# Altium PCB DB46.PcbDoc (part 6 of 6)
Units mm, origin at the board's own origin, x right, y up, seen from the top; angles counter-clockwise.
Board outline 82.2 x 113.2 mm, 8 copper layers (Top Layer, MidLayer1, MidLayer2, GND, MidLayer3, VCC, MidLayer4, Bottom Layer), stack 1.576 mm thick; 186 components, 477 nets, 1727 pads, 1538 vias.
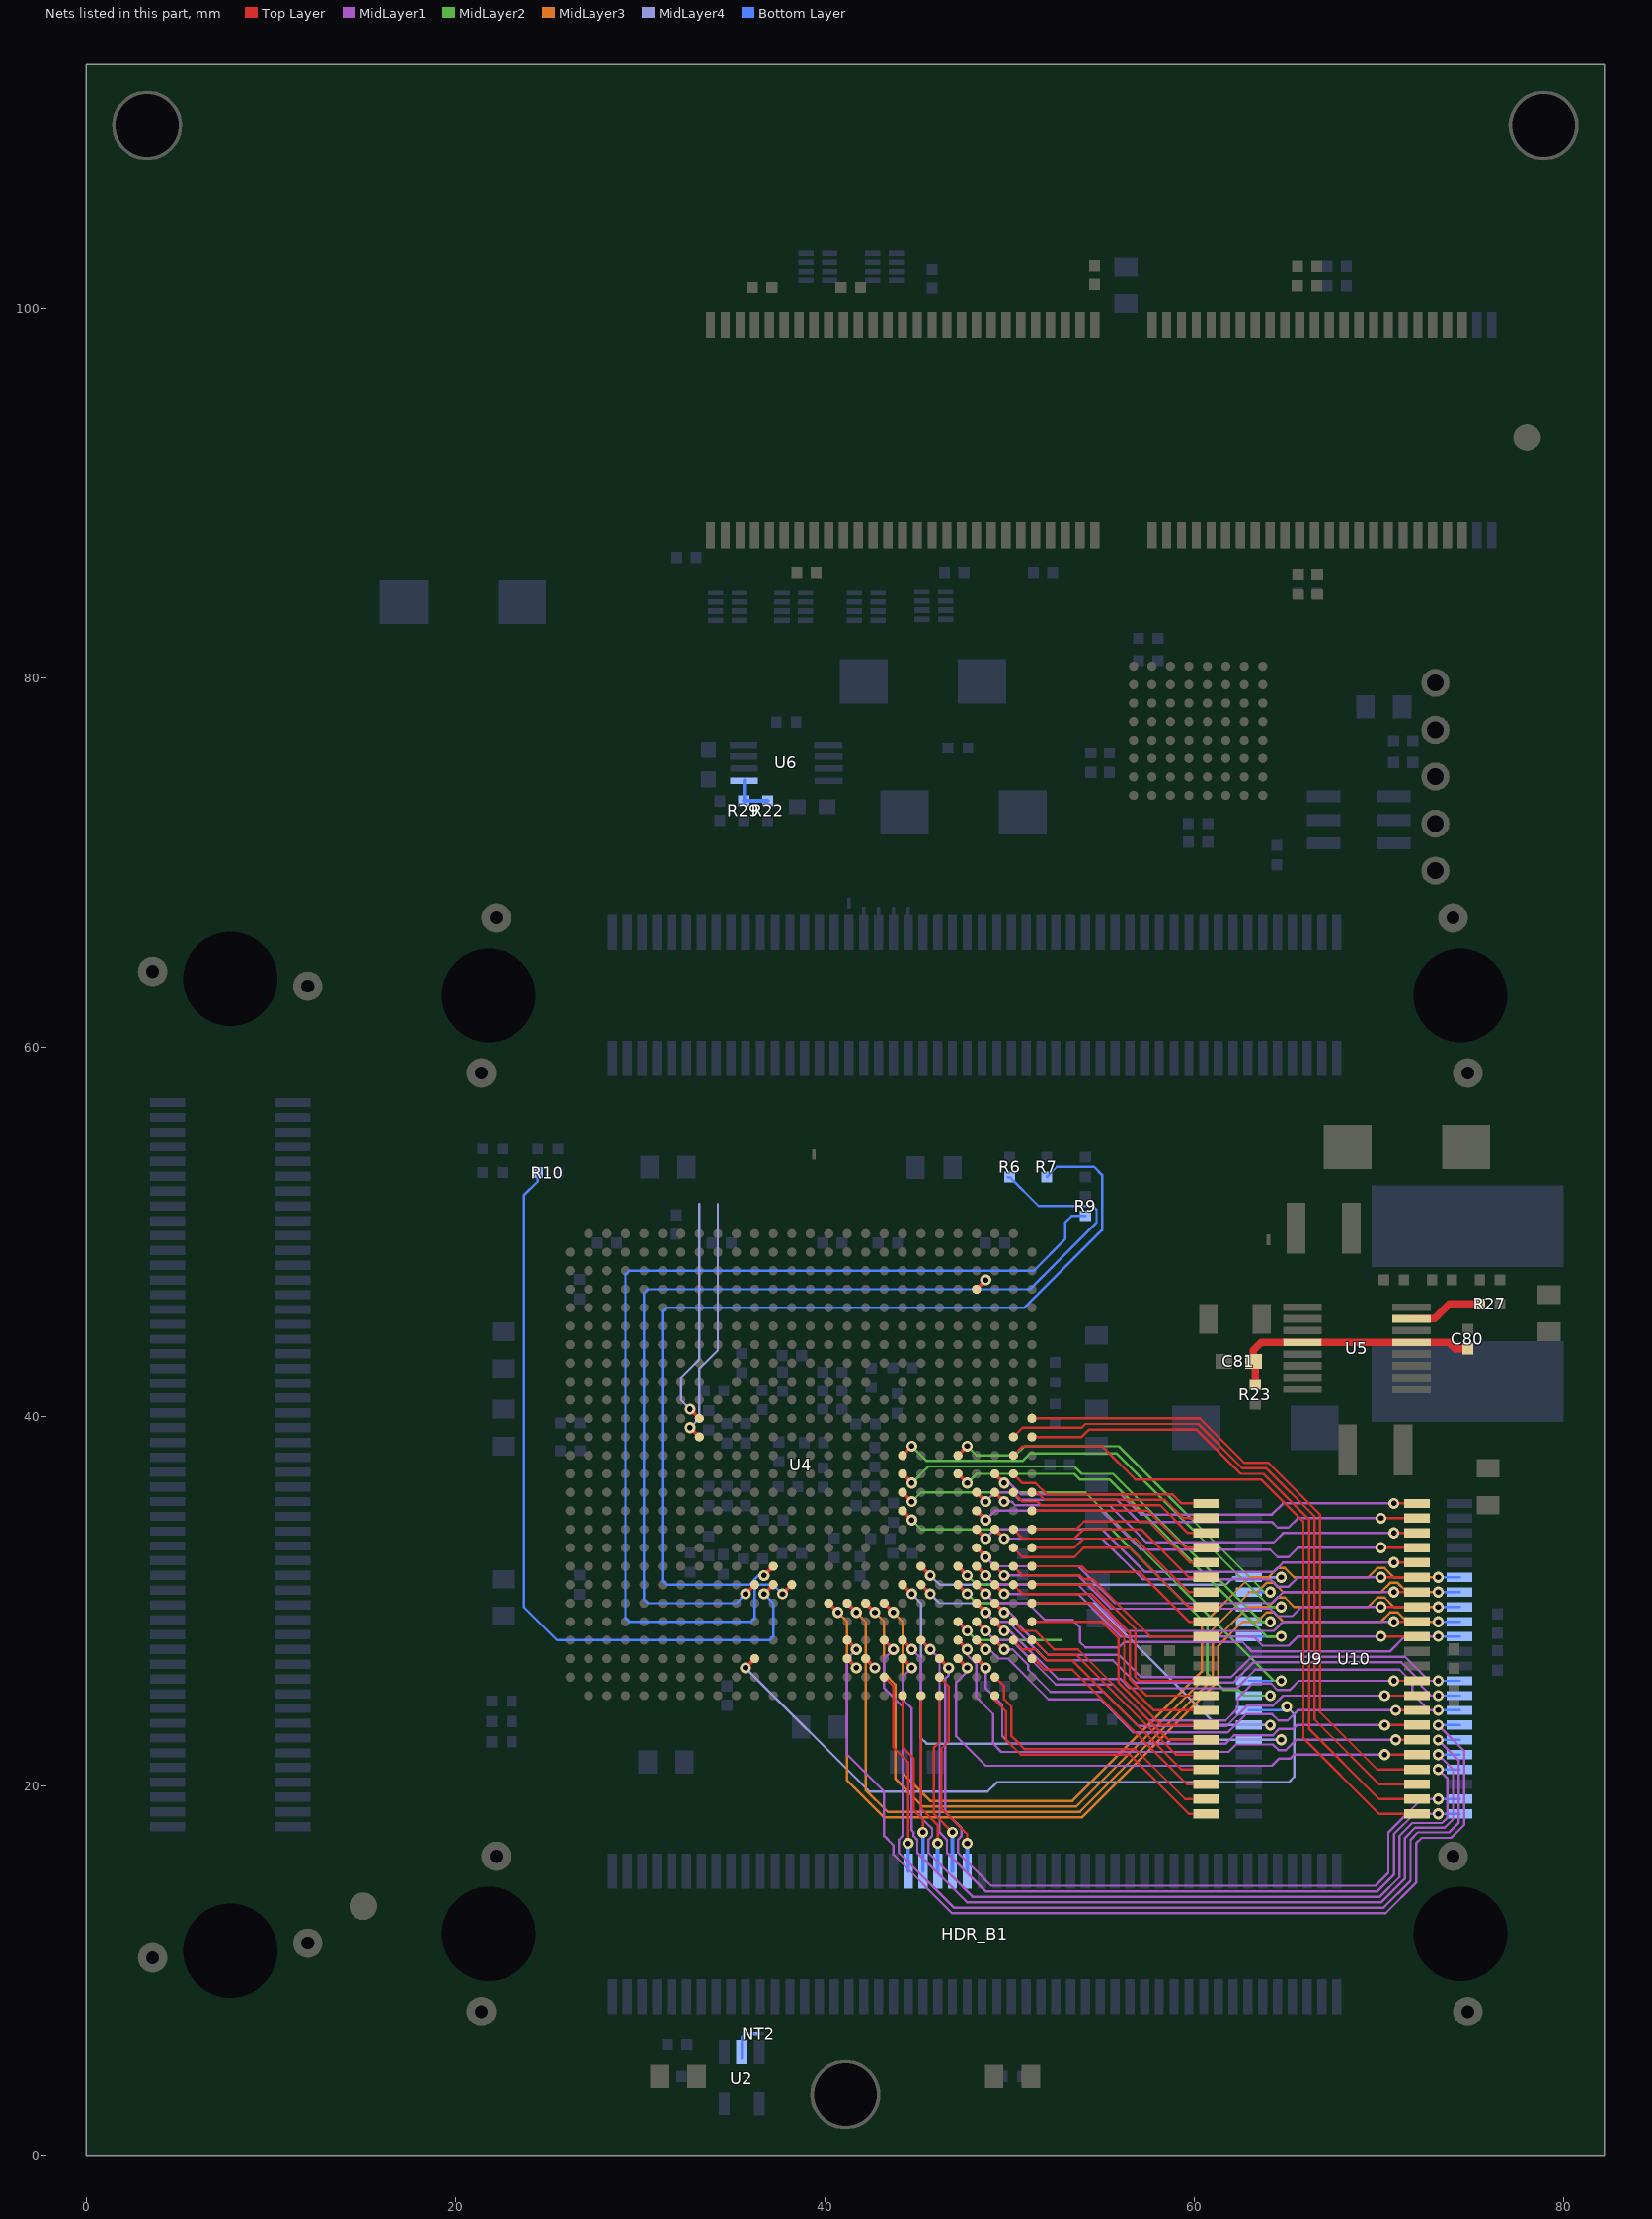
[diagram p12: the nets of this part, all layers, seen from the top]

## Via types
v1: diameter 0.6, hole 0.3, Top Layer to Bottom Layer, 904 vias
v2: diameter 0.6, hole 0.3, Top Layer to Bottom Layer, tented both sides, 506 vias
v3: diameter 0.7, hole 0.4, Top Layer to Bottom Layer, 127 vias
v4: diameter 0.6, hole 0.3, Top Layer to Bottom Layer, tented top, 1 vias

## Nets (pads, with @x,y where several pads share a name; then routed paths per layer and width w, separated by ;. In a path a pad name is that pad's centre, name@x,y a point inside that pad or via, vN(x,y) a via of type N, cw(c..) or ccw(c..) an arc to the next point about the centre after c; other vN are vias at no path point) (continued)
SRAM1_A16: U4.AD21 U10.43 | length 42.4
  Top Layer w0.2: U4.AD21@46.2,26.9 v1(46.7,26.4)
  MidLayer1 w0.127: v1(46.7,26.4) 46.7,26 46.5,25.8 46.5,23.3 46.5,23 46.5,18.6 47.4,17.7 47.4,17.3 47.2,17.1 47.2,16.4 48.994,14.606 69.806,14.606 70.5,15.3 70.5,17.5 72.3,19.3 v1(73.2,19.3)
  Bottom Layer w0.127: v1(73.2,19.3) U10.43@74.352,19.3
SRAM1_A17: U4.AC20 U10.44 | length 43.7
  Top Layer w0.2: U4.AC20@45.2,27.9 v1(45.7,27.4)
  MidLayer1 w0.127: v1(45.7,27.4) 46.2,26.9 46.2,23.3 46.2,23 46.2,17.5 46.6,17.1 46.6,16.4 48.694,14.306 69.906,14.306 70.8,15.2 70.8,17.4 71.9,18.5 v1(73.2,18.5)
  Bottom Layer w0.127: v1(73.2,18.5) U10.44@74.352,18.5
SRAM1_A18: U4.AA18 U10.28 | length 47.7
  Top Layer w0.2: U4.AA18@43.2,29.9 v1(43.7,29.4)
  MidLayer3 w0.127: v1(43.7,29.4) 44.2,28.9 44.2,23.3 44.2,23 44.2,20.7 45.7,19.2 53.4,19.2 60.4,26.2 60.4,28.7 63,31.3 64,31.3 64.5,31.8 64.9,31.8 65.4,31.3 69.4,31.3 69.9,31.8 70.3,31.8 70.8,31.3 v1(73.2,31.3)
  Bottom Layer w0.127: v1(73.2,31.3) U10.28@74.352,31.3
SRAM1_D0: U4.Y20 U10.7 | length 23.3
  Top Layer w0.2: U4.Y20@45.2,30.9 v1(45.7,30.4)
  MidLayer2 w0.127: v1@64.099,23.299 v1(64.105,23.299)
  MidLayer4 w0.127: v1(45.7,30.4) 46.2,29.9 52.8,29.9 53.1,29.9 54.6,29.9 61.2,23.299 v1(64.105,23.299)
  Bottom Layer w0.127: U10.7@62.952,23.3 v1(64.105,23.299) v1@64.205,23.299
SRAM1_D1: U4.AD11 U10.8 | length 39.7
  Top Layer w0.2: v1(35.7,26.4) U4.AD11@36.2,26.9
  MidLayer4 w0.127: v1(35.7,26.4) 42.4,19.7 48.8,19.7 49.3,20.2 65.1,20.2 65.4,20.5 65.4,23.9 v1(65,24.3)
  Bottom Layer w0.127: U10.8@62.952,24.1 64.8,24.1 v1(65,24.3)
  Bottom Layer w0.381: v1@35.592,26.4 v1(35.7,26.4)
SRAM1_D2: U4.T19 U10.9 | length 26.8
  Top Layer w0.2: U4.T19@44.2,34.9 v1(44.7,34.4)
  MidLayer2 w0.127: v1(44.7,34.4) 45.2,33.9 52.8,33.9 53.1,33.9 55.5,33.9 60.7,28.7 60.7,26.1 61.6,25.2 62.4,25.2 62.7,24.9 v1(64.105,24.9)
  Bottom Layer w0.127: U10.9@62.952,24.9 v1@64.205,24.9
SRAM1_D3: U4.R19 U10.10 | length 27
  Top Layer w0.2: U4.R19@44.2,35.9 v1(44.7,35.4)
  MidLayer2 w0.127: v1(44.7,35.4) 45.2,35.9 52.8,35.9 53.1,35.9 54.1,35.9 64.3,25.7 v1(64.7,25.7)
  Bottom Layer w0.127: U10.10@62.952,25.7 v1@64.8,25.7
SRAM1_D4: U4.P22 U10.13 | length 23.4
  Top Layer w0.2: U4.P22@47.2,36.9 v1(47.7,36.4)
  MidLayer2 w0.127: v1(47.7,36.4) 48.2,36.9 52.8,36.9 53.1,36.9 53.5,36.9 53.8,36.6 55.4,36.6 63.9,28.1 v1(64.7,28.1)
  Bottom Layer w0.127: U10.13@62.952,28.1 v1@64.8,28.1
SRAM1_D5: U4.P19 U10.14 | length 25.2
  Top Layer w0.2: U4.P19@44.2,36.9 v1(44.7,36.4)
  MidLayer2 w0.127: v1(44.7,36.4) 45.6,37.3 52.8,37.3 53.1,37.3 53.5,37.3 53.9,36.9 55.6,36.9 63.6,28.9 v1(64.105,28.9)
  Bottom Layer w0.127: U10.14@62.952,28.9 v1@64.205,28.9
SRAM1_D6: U4.N19 U10.15 | length 26.5
  Top Layer w0.178: U4.N19@44.2,37.9 v1(44.7,38.4)
  MidLayer2 w0.127: v1(44.7,38.4) 45.5,37.6 50.7,37.6 51.1,38 52.8,38 53.1,38 55.8,38 64.1,29.7 v1(64.7,29.7)
  Bottom Layer w0.127: U10.15@62.952,29.7 v1@64.8,29.7
SRAM1_D7: U4.N22 U10.16 | length 22.1
  Top Layer w0.2: U4.N22@47.2,37.9 v1(47.7,38.4)
  MidLayer2 w0.127: v1(47.7,38.4) 48.2,37.9 50.3,37.9 50.8,38.4 52.8,38.4 53.1,38.4 55.9,38.4 63.8,30.5 v1(64.105,30.5)
  Bottom Layer w0.127: U10.16@62.952,30.5 v1@64.205,30.5
SRAM1_D8: U4.AA17 U10.29 | length 48.3
  Top Layer w0.2: U4.AA17@42.2,29.9 v1(42.7,29.4)
  MidLayer3 w0.127: v1(42.7,29.4) 43.2,28.9 43.2,26.1 43.8,25.5 43.8,23.3 43.8,23 43.8,20.4 45.3,18.9 53.6,18.9 60.7,26 60.7,28.2 63,30.5 63.405,30.5 63.905,31 64.305,31 64.805,30.5 70.1,30.5 70.6,31 71,31 71.5,30.5 v1(73.2,30.5)
  Bottom Layer w0.127: v1(73.2,30.5) U10.29@74.352,30.5
SRAM1_D9: U4.AA16 U10.30 | length 49.8
  Top Layer w0.2: U4.AA16@41.2,29.9 v1(41.7,29.4)
  MidLayer3 w0.127: v1(41.7,29.4) 42.2,28.9 42.2,23.3 42.2,23 42.2,19.8 43.4,18.6 53.8,18.6 61,25.8 61,27.8 62.9,29.7 64,29.7 64.5,30.2 64.9,30.2 65.4,29.7 69.4,29.7 69.9,30.2 70.3,30.2 70.8,29.7 v1(73.2,29.7)
  Bottom Layer w0.127: v1(73.2,29.7) U10.30@74.352,29.7
SRAM1_D10: U4.AA15 U10.31 | length 50.3
  Top Layer w0.2: U4.AA15@40.2,29.9 v1(40.7,29.4)
  MidLayer3 w0.127: v1(40.7,29.4) 41.2,28.9 41.2,23.3 41.2,23 41.2,20.3 43.2,18.3 53.9,18.3 61.3,25.7 61.3,27.6 62.6,28.9 63.405,28.9 63.905,29.4 64.305,29.4 64.805,28.9 70.1,28.9 70.6,29.4 71,29.4 71.5,28.9 v1(73.2,28.9)
  Bottom Layer w0.127: v1(73.2,28.9) U10.31@74.352,28.9
SRAM1_D11: U4.Y23 U10.32 | length 28.7
  Top Layer w0.2: U4.Y23@48.2,30.9 v1(48.7,30.4)
  MidLayer1 w0.127: v1(48.7,30.4) 49.2,29.9 51,29.9 51.9,29 52.8,29 53.1,29 53.4,29 53.8,28.6 53.8,27.8 54.1,27.5 55.9,27.5 56.2,27.8 62.6,27.8 63.1,27.3 70.6,27.3 71.4,28.1 v1(73.2,28.1)
  Bottom Layer w0.127: v1(73.2,28.1) U10.32@74.352,28.1
SRAM1_D12: U4.AA24 U10.35 | length 27.9
  Top Layer w0.2: U4.AA24@49.2,29.9 v1(49.7,29.4)
  MidLayer1 w0.127: v1(49.7,29.4) 50,29.4 50.3,29.1 50.3,28.9 52.1,27.1 52.8,27.1 53.1,27.1 55.9,27.1 57.1,25.9 62,25.9 63.1,27 71.4,27 72.7,25.7 v1(73.2,25.7)
  Bottom Layer w0.127: v1(73.2,25.7) U10.35@74.352,25.7
SRAM1_D13: U4.AA23 U10.36 | length 29.3
  Top Layer w0.2: U4.AA23@48.2,29.9 v1(48.7,29.4)
  MidLayer1 w0.127: v1(48.7,29.4) 49.2,28.9 49.9,28.9 52,26.8 52.8,26.8 53.1,26.8 55.6,26.8 56.8,25.6 62.1,25.6 63.2,26.7 71.2,26.7 72.3,25.6 72.3,25.4 72.8,24.9 v1(73.2,24.9)
  Bottom Layer w0.127: v1(73.2,24.9) U10.36@74.352,24.9
SRAM1_D14: U4.AB24 U10.37 | length 28.3
  Top Layer w0.2: U4.AB24@49.2,28.9 v1(49.7,28.4)
  MidLayer1 w0.127: v1(49.7,28.4) 50,28.4 52.6,25.8 52.8,25.8 53.1,25.8 56,25.8 56.5,25.3 62.3,25.3 63.3,26.3 71.1,26.3 71.8,25.6 71.8,25 72.7,24.1 v1(73.2,24.1)
  Bottom Layer w0.127: v1(73.2,24.1) U10.37@74.352,24.1
SRAM1_D15: U4.AC16 U10.38 | length 55.6
  Top Layer w0.2: U4.AC16@41.2,27.9 v1(41.7,27.4)
  MidLayer1 w0.127: v1(41.7,27.4) 41.2,26.9 41.2,23.3 41.2,23 41.2,21.7 43.2,19.7 43.2,17.3 43.7,16.8 43.7,16.3 46.875,13.125 70.35,13.125 72,14.775 72,15.3 72,16.9 72.3,17.2 73.9,17.2 74.6,17.9 74.6,21.9 v1(73.2,23.3)
  Bottom Layer w0.127: v1(73.2,23.3) U10.38@74.352,23.3
SRAM1_NBHE: U4.AD19 U10.40 | length 49.5
  Top Layer w0.2: U4.AD19@44.2,26.9 v1(44.7,26.4)
  MidLayer1 w0.127: v1(44.7,26.4) 44.2,25.9 44.2,24.7 44.7,24.2 44.7,23.3 44.7,23 44.7,17.6 44.8,17.5 44.8,17.3 45,17.1 45,16.4 47.681,13.719 70.119,13.719 71.4,15 71.4,15.6 ; 71.4,15.6 71.4,17.2 71.946,17.746 73.546,17.746 74,18.2 74,20.9 v1(73.2,21.7)
  Bottom Layer w0.127: v1(73.2,21.7) U10.40@74.352,21.7
SRAM1_NBLE: U4.AC18 U10.39 | length 53.2
  Top Layer w0.2: U4.AC18@43.2,27.9 v1(43.7,27.4)
  MidLayer1 w0.127: v1(43.7,27.4) 43.2,26.9 43.2,25.3 44.2,24.3 44.2,23.3 44.2,23 44.2,17.3 44,17.1 44,16.4 46.975,13.425 70.25,13.425 71.7,14.875 71.7,15.4 71.7,17.1 72.092,17.492 73.792,17.492 74.3,18 74.3,21.4 v1(73.2,22.5)
  Bottom Layer w0.127: v1(73.2,22.5) U10.39@74.352,22.5
SRAM1_NCS: U4.Y19 U10.6 | length 30.3
  Top Layer w0.2: U4.Y19@44.2,30.9 v1(44.7,30.4)
  MidLayer4 w0.127: v1(44.7,30.4) 45.2,29.9 45.2,23.3 45.2,23 45.2,22.6 45.5,22.3 58.5,22.3 58.7,22.5 v1(64.7,22.5)
  Bottom Layer w0.127: U10.6@62.952,22.5 v1(64.7,22.5) v1@64.8,22.5
SRAM1_NOE: U4.AC19 U10.41 | length 51.3
  Top Layer w0.2: U4.AC19@44.2,27.9 v1(44.7,27.4)
  MidLayer1 w0.127: v1(44.7,27.4) 45.2,26.9 ; 45.2,24 45.2,26.9 ; v1(73.2,20.9) 73.7,20.4 73.7,18.3 73.4,18 71.8,18 71.1,17.3 71.1,15.7 71.1,15.075 70.037,14.012 47.987,14.012 45.6,16.4 45.6,17.1 45.8,17.3 45.8,17.7 45.7,17.8 45.2,18.3 45.2,23 45.2,23.3 45.2,26.9
  Bottom Layer w0.127: v1(73.2,20.9) U10.41@74.352,20.9
SRAM1_NWE: U4.W20 U10.17 | length 21.9
  Top Layer w0.2: U4.W20@45.2,31.9 v1(45.7,31.4)
  MidLayer4 w0.127: v1(45.7,31.4) 46.2,30.9 50.9,30.9 52.8,30.9 53.1,30.9 61.7,30.9 62.1,31.3 v1(64.7,31.3)
  Bottom Layer w0.127: U10.17@62.952,31.3 v1(64.7,31.3) v1@64.8,31.3
SRAM2_A0: U4.N25 U9.1 | length 37.2
  Top Layer w0.127: U4.N25@50.2,37.9 50.7,38.4 52.8,38.4 53.1,38.4 55,38.4 56.8,36.6 63.6,36.6 65.9,34.3 65.9,22.6 70,18.5 U9.1@72.052,18.5
SRAM2_A1: U4.M26 U9.2 | length 35.9
  Top Layer w0.127: U4.M26@51.2,38.9 52.8,38.9 53.1,38.9 53.9,38.9 54.3,39.3 60.1,39.3 62.5,36.9 63.737,36.9 66.2,34.437 66.2,23.1 70,19.3 U9.2@72.052,19.3
SRAM2_A2: U4.M25 U9.3 | length 36.7
  Top Layer w0.127: U4.M25@50.2,38.9 50.7,39.4 52.8,39.4 53.1,39.4 53.9,39.4 54.1,39.6 60.2,39.6 62.6,37.2 63.9,37.2 66.5,34.6 66.5,23.6 70,20.1 U9.3@72.052,20.1
SRAM2_A3: U4.L26 U9.4 | length 35
  Top Layer w0.127: U4.L26@51.2,39.9 52.8,39.9 53.1,39.9 60.3,39.9 62.7,37.5 64,37.5 66.8,34.7 66.8,24 69.9,20.9 U9.4@72.052,20.9
SRAM2_A4: U4.AD22 U9.5 | length 30.5
  Top Layer w0.127: v1(70.299,21.7) U9.5@72.052,21.7
  Top Layer w0.2: U4.AD22@47.2,26.9 v1(47.7,26.4)
  MidLayer1 w0.127: v1(47.7,26.4) 47.7,26.2 47.1,25.6 47.1,23.3 47.1,23 47.1,22.7 48.7,21.1 64.2,21.1 64.6,21.5 65.2,21.5 65.4,21.7 v1(70.299,21.7)
SRAM2_A5: U4.U23 U9.18 | length 25.4
  Top Layer w0.127: v1@70.8,32.1 U9.18@72.052,32.1
  Top Layer w0.2: U4.U23@48.2,33.9 v1(48.7,33.4)
  MidLayer1 w0.127: v1(48.7,33.4) 49.2,33.9 52.1,33.9 52.8,33.9 53.1,33.9 55,33.9 57.3,31.6 64.3,31.6 64.8,32.1 v1(70.8,32.1)
SRAM2_A6: U4.T23 U9.19 | length 25.5
  Top Layer w0.127: v1(70.1,32.9) U9.19@72.052,32.9
  Top Layer w0.2: U4.T23@48.2,34.9 v1(48.7,34.4)
  MidLayer1 w0.127: v1(48.7,34.4) 49.2,34.9 52.8,34.9 53.1,34.9 55,34.9 57.1,32.8 64.1,32.8 64.5,32.4 65.1,32.4 65.6,32.9 v1(70.1,32.9)
SRAM2_A7: U4.R24 U9.20 | length 24.2
  Top Layer w0.127: v1(70.8,33.7) U9.20@72.052,33.7
  Top Layer w0.2: U4.R24@49.2,35.9 v1(49.7,35.4)
  MidLayer1 w0.127: v1(49.7,35.4) 50.1,35.4 50.3,35.2 52.8,35.2 53.1,35.2 55.4,35.2 57.4,33.2 64.3,33.2 64.8,33.7 v1(70.8,33.7)
SRAM2_A8: U4.R23 U9.21 | length 25.3
  Top Layer w0.127: v1(70.1,34.5) U9.21@72.052,34.5
  Top Layer w0.2: U4.R23@48.2,35.9 v1(48.7,35.4)
  MidLayer1 w0.127: v1(48.7,35.4) 49.2,35.9 50.1,35.9 50.5,35.5 52.8,35.5 53.1,35.5 55.8,35.5 57,34.3 64.2,34.3 64.5,34 65.1,34 65.6,34.5 v1(70.1,34.5)
SRAM2_A9: U4.P24 U9.22 | length 24
  Top Layer w0.127: v1(70.8,35.3) U9.22@72.052,35.3
  Top Layer w0.2: U4.P24@49.2,36.9 v1(49.7,36.4)
  MidLayer1 w0.127: v1(49.7,36.4) 50,36.4 50.6,35.8 52.8,35.8 53.1,35.8 56,35.8 57.1,34.7 64.2,34.7 64.8,35.3 v1(70.8,35.3)
SRAM2_A10: U4.P25 U9.23 | length 11.1
  Top Layer w0.127: U4.P25@50.2,36.9 50.7,36.4 51.4,36.4 52,35.8 52.8,35.8 53.1,35.8 58.8,35.8 59.3,35.3 U9.23@60.6,35.3
SRAM2_A11: U4.R26 U9.24 | length 10
  Top Layer w0.127: U4.R26@51.2,35.9 51.5,35.9 51.9,35.5 52.8,35.5 53.1,35.5 58.4,35.5 59.4,34.5 U9.24@60.652,34.5
SRAM2_A12: U4.R25 U9.25 | length 11.4
  Top Layer w0.127: U4.R25@50.2,35.9 50.7,35.4 51.5,35.4 51.7,35.2 52.8,35.2 53.1,35.2 58.15,35.2 59.65,33.7 U9.25@60.652,33.7
SRAM2_A13: U4.T26 U9.26 | length 10.3
  Top Layer w0.127: U4.T26@51.2,34.9 52.8,34.9 53.1,34.9 57.5,34.9 59.5,32.9 U9.26@60.652,32.9
SRAM2_A14: U4.U26 U9.27 | length 10.6
  Top Layer w0.127: U4.U26@51.2,33.9 52.8,33.9 53.1,33.9 53.6,33.9 54.025,34.325 57.525,34.325 59.75,32.1 U9.27@60.652,32.1
SRAM2_A15: U4.AD26 U9.42 | length 12.3
  Top Layer w0.127: U4.AD26@51.2,26.9 51.3,26.9 51.9,26.3 52.8,26.3 53.1,26.3 53.4,26.3 59.6,20.1 U9.42@60.652,20.1
SRAM2_A16: U4.AE24 U9.43 | length 15.6
  Top Layer w0.127: U4.AE24@49.2,25.9 49.7,25.4 49.7,24.7 50.1,24.3 50.1,23.3 50.1,23 50.1,22.7 50.8,22 56.8,22 59.5,19.3 U9.43@60.7,19.3
SRAM2_A17: U4.AF24 U9.44 | length 15.2
  Top Layer w0.127: U4.AF24@49.2,24.9 49.2,24.65 49.8,24.05 49.8,23.3 49.8,23 49.8,22.5 50.6,21.7 56.5,21.7 59.7,18.5 U9.44@60.7,18.5
SRAM2_A18: U4.U25 U9.28 | length 11.9
  Top Layer w0.127: U4.U25@50.2,33.9 50.7,33.4 52.8,33.4 53.1,33.4 53.5,33.4 54,33.9 57.1,33.9 59.7,31.3 U9.28@60.652,31.3
SRAM2_D0: U4.AD23 U9.7 | length 27.8
  Top Layer w0.127: v1(70.299,23.3) U9.7@72.052,23.3
  Top Layer w0.2: U4.AD23@48.2,26.9 v1(48.7,26.4)
  MidLayer1 w0.127: v1(48.7,26.4) 48.7,25.3 49.6,24.4 49.6,23.3 49.6,23 49.6,22.7 50,22.3 61.7,22.3 62.15,22.75 64.25,22.75 64.6,23.1 65.35,23.1 65.55,23.3 v1(70.299,23.3)
SRAM2_D1: U4.AC23 U9.8 | length 26.7
  Top Layer w0.127: v1(70.9,24.1) U9.8@72.052,24.1
  Top Layer w0.2: U4.AC23@48.2,27.9 v1(48.7,27.4)
  MidLayer1 w0.127: v1(48.7,27.4) 48.9,27.4 49.4,26.9 49.9,26.9 52.1,24.7 52.8,24.7 53.1,24.7 54.9,24.7 56.7,22.9 61.8,22.9 62.8,23.9 64.2,23.9 64.55,23.55 65.05,23.55 65.6,24.1 v1(70.9,24.1)
SRAM2_D2: U4.AC24 U9.9 | length 25.6
  Top Layer w0.127: v1(70.299,24.9) U9.9@72.052,24.9
  Top Layer w0.2: U4.AC24@49.2,27.9 v1(49.7,27.4)
  MidLayer1 w0.127: v1(49.7,27.4) 50.15,27.4 51,26.55 51,26.3 52.2,25.1 52.8,25.1 53.1,25.1 55.1,25.1 56.95,23.25 61.75,23.25 62.85,24.35 64.25,24.35 64.8,24.9 v1(70.299,24.9)
SRAM2_D3: U4.AB23 U9.10 | length 27.6
  Top Layer w0.127: v1(70.8,25.7) U9.10@72.052,25.7
  Top Layer w0.2: U4.AB23@48.2,28.9 v1(48.7,28.4)
  MidLayer1 w0.127: v1(48.7,28.4) 49.2,27.9 50.1,27.9 52.5,25.5 52.8,25.5 53.1,25.5 55.6,25.5 57.55,23.55 61.691,23.55 62.35,24.209 62.35,24.75 63.15,25.55 64.15,25.55 64.5,25.2 65.15,25.2 65.65,25.7 v1(70.8,25.7)
SRAM2_D4: U4.Y24 U9.13 | length 24.4
  Top Layer w0.127: v1(70.1,28.1) U9.13@72.052,28.1
  Top Layer w0.2: U4.Y24@49.2,30.9 v1(49.7,30.4)
  MidLayer1 w0.127: v1(49.7,30.4) 52.8,30.4 53.1,30.4 53.7,30.4 56,28.1 63.2,28.1 63.7,27.6 65.1,27.6 65.6,28.1 v1(70.1,28.1)
SRAM2_D5: U4.W23 U9.14 | length 25.5
  Top Layer w0.127: v1(70.8,28.9) U9.14@72.052,28.9
  Top Layer w0.2: U4.W23@48.2,31.9 v1(48.7,31.4)
  MidLayer1 w0.127: v1(48.7,31.4) 49.2,30.9 52.8,30.9 53.1,30.9 53.7,30.9 56.2,28.4 64.3,28.4 64.8,28.9 v1(70.8,28.9)
SRAM2_D6: U4.W24 U9.15 | length 24.2
  Top Layer w0.127: U4.W24@49.2,31.9 v1(49.7,31.4) ; v1(70.1,29.7) U9.15@72.052,29.7
  MidLayer1 w0.127: v1(49.7,31.4) 52.8,31.4 53.1,31.4 53.7,31.4 55.5,29.6 64.1,29.6 64.5,29.2 65.3,29.2 65.8,29.7 v1(70.1,29.7)
SRAM2_D7: U4.V23 U9.16 | length 25.3
  Top Layer w0.127: v1(70.8,30.5) U9.16@72.052,30.5
  Top Layer w0.2: U4.V23@48.2,32.9 v1(48.7,32.4)
  MidLayer1 w0.127: v1(48.7,32.4) 49.2,31.9 52.8,31.9 53.1,31.9 53.7,31.9 55.7,29.9 64.2,29.9 64.8,30.5 v1(70.8,30.5)
SRAM2_D8: U4.V26 U9.29 | length 10.9
  Top Layer w0.127: U4.V26@51.2,32.9 52.8,32.9 53.1,32.9 53.5,32.9 54,33.4 56.8,33.4 59.7,30.5 U9.29@60.652,30.5
SRAM2_D9: U4.V25 U9.30 | length 12.2
  Top Layer w0.127: U4.V25@50.2,32.9 50.7,32.4 52.8,32.4 53.1,32.4 53.5,32.4 54,32.9 56.5,32.9 59.7,29.7 U9.30@60.652,29.7
SRAM2_D10: U4.W26 U9.31 | length 10.7
  Top Layer w0.127: U4.W26@51.2,31.9 52.8,31.9 53.1,31.9 53.9,31.9 54.2,31.6 57,31.6 59.7,28.9 U9.31@60.652,28.9
SRAM2_D11: U4.W25 U9.32 | length 12
  Top Layer w0.127: U4.W25@50.2,31.9 50.7,31.4 52.8,31.4 53.1,31.4 53.8,31.4 54,31.2 54.5,31.2 57.6,28.1 U9.32@60.652,28.1
SRAM2_D12: U4.Y26 U9.35 | length 13.1
  Top Layer w0.127: U4.Y26@51.2,30.9 52.8,30.9 53.1,30.9 54.4,30.9 56.8,28.5 56.8,25.9 57,25.7 U9.35@60.652,25.7
SRAM2_D13: U4.Y25 U9.36 | length 14.4
  Top Layer w0.127: U4.Y25@50.2,30.9 50.7,30.4 52.3,30.4 ; 52.3,30.4 53.6,30.4 54.4,30.4 56.5,28.3 56.5,25.8 57.4,24.9 U9.36@60.652,24.9
SRAM2_D14: U4.AA26 U9.37 | length 13.3
  Top Layer w0.127: U4.AA26@51.2,29.9 51.7,29.9 53.2,29.9 53.5,29.9 54.399,29.9 56.2,28.099 56.2,25.7 57.8,24.1 U9.37@60.652,24.1
SRAM2_D15: U4.AB26 U9.38 | length 13.2
  Top Layer w0.127: U4.AB26@51.2,28.9 52.5,28.9 52.8,28.9 55,28.9 55.9,28 55.9,25.6 58.2,23.3 U9.38@60.652,23.3
SRAM2_NBHE: U4.AC26 U9.40 | length 12
  Top Layer w0.127: U4.AC26@51.2,27.9 51.3,27.9 52.1,27.1 52.8,27.1 53.1,27.1 53.6,27.1 55.3,25.4 59,21.7 U9.40@60.652,21.7
SRAM2_NBLE: U4.AB25 U9.39 | length 13.1
  Top Layer w0.127: U4.AB25@50.2,28.9 50.7,28.4 51.4,28.4 52.4,27.4 52.8,27.4 53.1,27.4 53.7,27.4 55.6,25.5 58.6,22.5 U9.39@60.652,22.5
SRAM2_NCS: U4.AC22 U9.6 | length 30
  Top Layer w0.127: v1(70.9,22.5) U9.6@72.052,22.5
  Top Layer w0.2: U4.AC22@47.2,27.9 v1(47.7,27.4)
  MidLayer1 w0.127: v1(47.7,27.4) 47.7,27.1 48.2,26.6 48.2,24.8 49.1,23.9 49.1,23.3 49.1,23 49.1,22.3 49.55,21.85 61.85,21.85 62.25,22.25 64.25,22.25 64.55,21.95 64.95,21.95 65.5,22.5 v1(70.9,22.5)
SRAM2_NOE: U4.AC25 U9.41 | length 13.4
  Top Layer w0.127: U4.AC25@50.2,27.9 50.7,27.4 51.4,27.4 52,26.8 52.8,26.8 53.1,26.8 53.4,26.8 59.3,20.9 U9.41@60.652,20.9
SRAM2_NWE: U4.U24 U9.17 | length 24.3
  Top Layer w0.127: v1(70.1,31.3) U9.17@72.052,31.3
  Top Layer w0.2: U4.U24@49.2,33.9 v1(49.7,33.4)
  MidLayer1 w0.127: v1(49.7,33.4) 52.8,33.4 53.1,33.4 55,33.4 57.2,31.2 64.1,31.2 64.5,30.8 65.1,30.8 65.6,31.3 v1(70.1,31.3)
STATUS_LED: NT2.1 U2.2 | length 1.9
  Bottom Layer w0.127: U2.2@35.5,5.275 U2.2@35.5,5.6 35.5,6.4 35.675,6.575 NT2.1@36.2,6.575
SW0: HDR_B1.42 U4.AE18 | length 11
  Top Layer w0.127: U4.AE18@43.2,25.9 43.7,25.4 43.7,23.3 43.7,23 43.7,22.1 44.5,21.3 v2(44.5,16.9)
  Bottom Layer w0.2: HDR_B1.42@44.5,15.4 v2(44.5,16.9)
SW1: HDR_B1.44 U4.AF19 | length 10
  Top Layer w0.127: U4.AF19@44.2,24.9 44.2,23.3 44.2,23 44.2,22.1 44.8,21.5 44.8,18.7 45.3,18.2 v2(45.3,17.5)
  Bottom Layer w0.2: HDR_B1.44@45.3,15.4 v2(45.3,17.5)
SW2: HDR_B1.46 U4.AF20 | length 9.9
  Top Layer w0.127: U4.AF20@45.2,24.9 45.2,23.3 45.2,23 45.2,18.8 46.1,17.9 v2(46.1,16.9)
  Bottom Layer w0.2: HDR_B1.46@46.1,15.4 v2(46.1,16.9)
SW3: HDR_B1.48 U4.AF21 | length 10
  Top Layer w0.127: U4.AF21@46.2,24.9 46.2,23.3 46.2,23 46.2,22.4 45.9,22.1 45.9,18.5 v2@46.9,17.5
  Bottom Layer w0.2: HDR_B1.48@46.9,15.4 v2(46.9,17.5)
SW4: HDR_B1.50 U4.AE21 | length 11.5
  Top Layer w0.127: U4.AE21@46.2,25.9 46.7,25.4 46.7,23.3 46.7,23 46.7,22.425 46.3,22.025 46.3,18.8 47.7,17.4 v2(47.7,16.9)
  Bottom Layer w0.2: HDR_B1.50@47.7,15.4 v2(47.7,16.9)
TCK: R7.2 U4.W12 | length 53.1
  Top Layer w0.2: v1(36.7,31.4) U4.W12@37.2,31.9
  Bottom Layer w0.127: v1(36.7,31.4) 36.4,31.4 35.9,30.9 31.4,30.9 31.2,31.1 31.2,45.7 31.4,45.9 50.8,45.9 55,50.1 55,53.076 54.56,53.515 52.553,53.515 R7.2@52,52.962
TDI: R10.2 U4.Y12 | length 41.4
  Top Layer w0.2: v1(36.7,30.4) U4.Y12@37.2,30.9
  Bottom Layer w0.127: R10.2@24.462,53.2 24.462,52.738 23.7,51.976 23.7,29.7 25.5,27.9 37,27.9 37.2,28.1 37.2,29.9 v1(36.7,30.4)
TDO: R9.2 U4.Y13 | length 56.7
  Top Layer w0.2: v1(37.7,30.4) U4.Y13@38.2,30.9
  Bottom Layer w0.127: v1(37.7,30.4) 37.2,30.9 36.3,30.9 36.2,30.8 36.2,29.1 36,28.9 29.4,28.9 29.2,29.1 29.2,33.7 29.2,47.7 29.4,47.9 30.4,47.9 51.3,47.9 53,49.6 53,50.5 53.362,50.862 R9.2@54.1,50.862
TMS: R6.2 U4.Y11 | length 55.3
  Top Layer w0.2: v1(35.7,30.4) U4.Y11@36.2,30.9
  Bottom Layer w0.127: v1(35.7,30.4) 35.2,29.9 30.4,29.9 30.2,30.1 30.2,46.7 30.4,46.9 51.1,46.9 54.7,50.5 54.7,51.2 54.5,51.4 51.562,51.4 R6.2@50,52.962 ; R6.2@49.9,52.962 R6.2@49.905,52.939
TOFF: R27.1 U5.7 | length 4.1
  Top Layer w0.4: U5.7@71.744,45.294 71.75,45.3 73,45.3 73.8,46.1 R27.1@75.462,46.1
UNUSED1: U4.D23 | length 0.7
  Top Layer w0.2: U4.D23@48.2,46.9 v1(48.7,47.4)
UNUSED2: U4.AB22 | length 6
  Top Layer w0.2: U4.AB22@47.2,28.9 v1(47.7,28.4)
  MidLayer2 w0.127: v1(47.7,28.4) 48.2,27.9 52.8,27.9
UNUSED3: U4.Y22 | length 6
  Top Layer w0.2: U4.Y22@47.2,30.9 v1(47.7,30.4)
  MidLayer2 w0.127: v1(47.7,30.4) 48.2,29.9 52.8,29.9
UNUSED4: U4.M8 | length 13.4
  Top Layer w0.2: v1(32.7,39.4) U4.M8@33.2,38.9
  MidLayer4 w0.127: v1(32.7,39.4) 33.2,39.9 33.2,42.6 34.2,43.6 34.2,51.5
UNUSED5: U4.L8 | length 12.4
  Top Layer w0.2: v1(32.7,40.4) U4.L8@33.2,39.9
  MidLayer4 w0.127: v1(32.7,40.4) 32.2,40.9 32.2,42.1 33.2,43.1 33.2,51.5
UNUSED6: U4.W22 | length 6
  Top Layer w0.2: U4.W22@47.2,31.9 v1(47.7,31.4)
  MidLayer2 w0.127: v1(47.7,31.4) 48.2,30.9 52.8,30.9
VFILT: C80.1 C81.1 R23.2 U5.5 U5.12 | length 13.8
  Top Layer w0.4: R23.2@63.3,41.738 63.3,42.9 C81.1@63.2,43 63.2,43.6 63.624,44.024 U5.12@65.852,44.024 ; U5.12@65.852,44.024 U5.5@71.744,44.024 73.775,44.025 74.125,43.675 C80.1@74.8,43.675
VRN_7: U4.AD17 | length 0.7
  Top Layer w0.2: U4.AD17@42.2,26.9 v1(42.7,26.4)
VRP_7: U4.AD16 | length 0.8
  Top Layer w0.2: U4.AD16@41.2,26.9 v1(41.7,26.4)
  Bottom Layer w0.381: v1@41.592,26.4 v1(41.7,26.4)
VSET: R22.1 R29.1 U6.5 | length 2.4
  Bottom Layer w0.203: R29.1@35.6,73.338 R22.1@36.9,73.338 ; R29.1@35.625,73.363 U6.5@35.625,74.425
pads on no net: FD1.0 FD2.0 HDR_B1.93 HDR_B1.95 HDR_B1.MH5 HDR_B1.MH6 HDR_L1.MH5 HDR_L1.MH6 HDR_T1.95 HDR_T1.MH5 HDR_T1.MH6 MH1.MOUNT MH2.MOUNT MH3.MOUNT U1.5 U2.1 U3.A1 U3.A8 U3.B1 U3.B4 U3.C1 U3.D1 U3.E1 U3.F8 U3.G1 U3.G8 U3.H1 U3.H8 U4.A3 U4.A4 U4.A5 U4.A11 U4.AD7 U4.AD20 U4.AD25 U4.AE7 U4.AE20 U4.B3 U4.B4 U4.C5 U4.D5 U4.E7 U4.E9 U4.G5 U4.G6 U4.G11 U4.G13 U4.G21 U4.G22 U4.H7 U4.H8 U4.H12 U4.H13 U4.N24 U4.R5 U4.R6 U4.R21 U4.R22 U4.T21 U4.W13 U4.Y14 U7.40 U8.40
copper on no net: | length 13.1
  Top Layer w0.127: v1(31.7,25.4) 32.2,25.9 ; 45.2,25.9 v1(45.7,25.4)
  Top Layer w0.2: v1(29.7,35.4) 30.2,35.9 ; v1(29.7,44.4) 30.2,43.9 ; v1(30.7,35.4) 31.2,35.9 ; v1(30.7,44.4) 31.2,43.9 ; v1(31.7,26.4) 32.2,26.9 ; 38.2,43.9 38.2,43.925 ; 39.2,30.85 39.2,30.9 ; 45.2,26.9 v1(45.7,26.4) ; 46.2,34.9 v1(46.7,34.4) ; 46.2,35.9 v1(46.7,35.4) ; 46.2,43.9 v1(46.7,44.4) ; 47.2,35.9 v1(47.7,35.4) ; 47.2,43.9 v1(47.7,44.4) ; 49.2,37.9 v1(49.7,38.4)
  MidLayer1 w0.127: v1(49.7,38.4) 52.8,38.4
  Bottom Layer w0.2: v1@45.7,26.361 v1(45.7,26.4)
  other v1: 41.1,1.1 39.544,1.744 42.656,1.744 38.9,3.3 43.3,3.3 39.544,4.856 42.656,4.856 41.1,5.5 3.3,107.7 78.9,107.7 1.744,108.344 4.856,108.344 77.344,108.344 80.456,108.344 1.1,109.9 5.5,109.9 76.7,109.9 81.1,109.9 1.744,111.456 4.856,111.456 77.344,111.456 80.456,111.456 3.3,112.1 78.9,112.1

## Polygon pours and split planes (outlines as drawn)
AGND on Top Layer "Toplayer- AGND" (solid, remove dead copper, pour order 1000): 60.391,52.77 60.391,42.6 78.443,42.6 78.443,52.77
GND on Top Layer "GROUND-TOP-LAYER" (solid, remove dead copper, pour order 1009): 0.5,104.968 7.587,104.968 7.587,112 74.412,112 74.412,104.968 81.5,104.968 81.5,0.5 46.062,0.5 46.062,7.531 35.937,7.531 35.937,0.5 0.5,0.5
1V2 on MidLayer1 "MidLayer1-1V2" (solid, remove dead copper, pour order 1002): 32.2,45 48.6,45 48.2,44.6 48.2,29.9 32.5,29.9 32.2,29.9 32.2,36 18.4,36 18.4,39.4 32.2,39.4
1V2 on MidLayer1 "1V2 Power" (solid, remove dead copper, pour order 1003): 79.3,56.1 79.3,35.7 43.603,35.7 43.5,35.6 43.5,38.6 54.919,38.6 55.228,38.9 61.4,44.9 61.4,47.8 61.4,55.8 61.091,56.1 79.3,56.1
GND on MidLayer1 "GROUND-MID1-LAYER" (solid, remove dead copper, pour order 1005): 0.5,104.968 7.587,104.968 7.587,112 74.412,112 74.412,104.968 81.5,104.968 81.5,0.5 46.062,0.5 46.062,7.531 35.937,7.531 35.937,0.5 0.5,0.5
GND on MidLayer2 "GROUND-MID2-LAYER" (solid, remove dead copper, pour order 1006): 0.5,104.968 7.587,104.968 7.587,112 74.412,112 74.412,104.968 81.5,104.968 81.5,0.5 46.062,0.5 46.062,7.531 35.937,7.531 35.937,0.5 0.5,0.5
GND on MidLayer3 "GROUND-MID3-LAYER" (solid, remove dead copper, pour order 1007): 0.5,104.968 7.587,104.968 7.587,112 74.412,112 74.412,104.968 81.5,104.968 81.5,0.5 46.062,0.5 46.062,7.531 35.937,7.531 35.937,0.5 0.5,0.5
2V5 on MidLayer4 "2V5 Plane" (solid, remove dead copper, pour order 1001): 48,22.8 48,50.1 38.735,58.166 38.735,71.374 42.418,71.374 42.418,78.105 47.498,78.105 47.498,81.534 34.925,81.534 26.6,73.8 21.7,68.9 21.7,54.1 26.7,54.1 31.4,49.5 31.4,22.8
GND on MidLayer4 "MidLayer4-GND" (solid, remove dead copper, pour order 1004): 0.4,112.7 0.5,112.8 81.6,112.8 81.6,0.5 0.5,0.5
GND on Bottom Layer "GROUND-BOTTOM-LAYER" (solid, remove dead copper, pour order 1008): 0.5,104.968 7.587,104.968 7.587,112 74.412,112 74.412,104.968 81.5,104.968 81.5,0.5 46.062,0.5 46.062,7.531 35.937,7.531 35.937,0.5 0.5,0.5
GND on GND (split plane): 81.689,112.689 81.689,0.51 0.51,0.51 0.51,112.689 38.7,112.689
3V3 on VCC (split plane): 38.7,112.689 68.627,112.689 68.627,103.155 68.635,103.09 68.66,103.029 68.7,102.977 69.113,102.565 69.135,102.547 69.165,102.525 69.226,102.499 69.291,102.491 77.264,102.491 78.894,100.86 78.894,58.905 77.841,57.852 74.204,57.852 71.178,60.878 71.126,60.918 71.065,60.943 71,60.952 66.8,60.952 66.735,60.943 66.674,60.918 66.622,60.878 66.472,60.728 66.432,60.676 66.406,60.615 66.398,60.55 66.398,56.054 61.722,51.378 61.682,51.326 61.656,51.265 61.648,51.2 61.648,40.4 61.656,40.335 61.682,40.274 61.722,40.222 62.122,39.822 62.174,39.782 62.235,39.756 62.3,39.748 65.6,39.748 65.665,39.756 65.726,39.782 65.778,39.822 66.504,40.548 68.889,40.548 69.217,40.22 69.217,36.576 69.225,36.511 69.251,36.45 69.291,36.398 69.418,36.271 69.47,36.231 69.531,36.205 69.596,36.197 76.346,36.197 77.348,35.195 77.348,32.7 77.348,31.6 77.348,20.204 74.895,17.752 72.1,17.752 72.035,17.743 71.974,17.718 71.922,17.678 70.622,16.378 70.582,16.326 70.556,16.265 70.548,16.2 70.548,13.304 66.472,9.228 66.432,9.176 66.406,9.115 66.398,9.05 66.398,0.51 0.51,0.51 0.51,112.689 38.7,112.689
5V0 on VCC (split plane): 81.689,112.689 81.689,0.51 66.902,0.51 66.902,8.945 70.978,13.022 71.018,13.074 71.043,13.135 71.052,13.2 71.052,16.095 72.204,17.248 75,17.248 75.065,17.256 75.126,17.282 75.178,17.322 77.778,19.922 77.801,19.951 77.818,19.974 77.826,19.992 77.843,20.035 77.852,20.1 77.852,31.6 77.852,32.7 77.852,35.3 77.843,35.365 77.818,35.426 77.796,35.456 77.778,35.478 76.629,36.627 76.577,36.667 76.516,36.692 76.451,36.701 69.721,36.701 69.721,40.325 69.712,40.39 69.687,40.451 69.647,40.503 69.172,40.978 69.12,41.018 69.059,41.043 68.994,41.052 66.4,41.052 66.335,41.043 66.274,41.018 66.222,40.978 65.495,40.252 62.404,40.252 62.152,40.504 62.152,51.095 66.828,55.772 66.868,55.824 66.893,55.885 66.902,55.95 66.902,60.445 66.904,60.448 70.895,60.448 73.922,57.422 73.944,57.404 73.974,57.382 74.035,57.356 74.1,57.348 77.945,57.348 78.011,57.356 78.071,57.382 78.124,57.422 79.325,58.623 79.365,58.675 79.39,58.736 79.398,58.801 79.398,100.965 79.39,101.03 79.365,101.091 79.342,101.121 79.325,101.143 77.547,102.921 77.494,102.961 77.434,102.986 77.368,102.995 69.396,102.995 69.131,103.26 69.131,112.689

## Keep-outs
Bottom Layer:
  rectangle: 33.297,106.543 38.297,108.943
  rectangle: 6.5,80 11.5,82.4
  rectangle: 67.15,84.7 72.15,86.8
Keep-Out Layer:
  circle w0.4: c74.392,62.8 r3
  circle w0.4: c21.792,62.8 r3
  circle w0.4: c7.792,63.7 r3
  circle w0.4: c7.792,11.1 r3
  circle w0.4: c21.792,12 r3
  circle w0.4: c74.392,12 r3
  region: 0,113.2 0,112.6 82.2,112.6 82.2,113.2
  rectangle: 0,0 82.2,0.6
  rectangle: 0,0 0.6,113.2
  region: 82.2,113.2 81.6,113.2 81.6,0 82.2,0

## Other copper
Top Layer:
  rectangle net AGND: 63.896,48.646 64.099,49.337
  rectangle net GND: 76.5,34.7 77,35.7
  rectangle net 5V0: 71.3,36.821 75.06,39.573
  rectangle net 5V0: 73.289,37.573 76.631,43.189
  region net LX: 70.325,43.6 67.2,43.6 67.2,41.207 70.325,41.207
  rectangle net 1V2: 72.4,53.34 76.9,55.753
  rectangle net GND: 78.575,45.049 79.822,45.349
  rectangle net GND: 67.2,64.8 69.6,68.4
  rectangle net 5V0: 67.2,57.2 69.6,60.8
  pour cut-out: 25.284,50.992 52.208,50.992 52.208,24.068 25.284,24.068
Bottom Layer:
  rectangle net 1V2: 67.085,48.304 70.8,51.913
  rectangle net 5V0: 67.2,6.4 69.6,8.8
  rectangle net LX: 67,41.1 71.1,43.9
  rectangle net 1V2: 72.4,50.1 76.9,55.7
  region net LX: 62.377,48.776 62.377,51.824 58.567,51.824 58.567,48.776
  rectangle net 3V3: 65.1,14.5 66.3,17.9
  rectangle net GND: 67.2,15.2 69.6,17.7
  rectangle net GND: 67.2,66 69.6,68.5
  rectangle net 5V0: 67.2,57.1 69.6,59.6
  rectangle net 5V0: 66.8,57.1 69.6,59.6
GND (plane layer: these items are gaps in the copper):
  text "GND" at 41.8,11.1 h1.52
VCC (plane layer: these items are gaps in the copper):
  lines w0.5: 66.65,0 66.65,9.05 70.8,13.2 70.8,16.2 72.1,17.5 75,17.5 77.6,20.1 77.6,31.6 77.6,32.7 77.6,35.3 76.451,36.449 69.596,36.449 69.469,36.576 69.469,40.325 68.994,40.8 66.4,40.8 65.6,40 62.3,40 61.9,40.4 61.9,51.2 66.65,55.95 66.65,60.55 66.8,60.7 71,60.7 74.1,57.6 77.945,57.6 79.146,58.801 79.146,100.965 77.368,102.743 69.291,102.743 68.879,103.155 68.879,113.2
  text "5V0" at 70.9,46.4 h1.52
  text "3V3" at 42.1,11.1 h1.52

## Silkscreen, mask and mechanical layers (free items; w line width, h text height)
Top Overlay:
  rectangle: 33.05,89 55.35,91.35
  rectangle: 56.85,88.975 75.359,91.325
  rectangle: 75.7,106.2 82.1,106.7
  rectangle: 72.8,106.2 75.7,113.2
  region: 47,112.975 43.025,112.975 43.025,106.2 47,106.2
  region: 75.4,112.75 75.4,113.2 43.025,113.2 43.025,112.75
  region: 75.8,106.2 75.8,107.025 43.025,107.025 43.025,106.2
  region: 42.925,106.2 42.925,113.2 42.425,113.2 42.425,106.2
  region: 40.6,106.2 40.6,113.2 40.475,113.2 40.475,106.2
  region: 41.1,106.2 41.1,113.2 40.9,113.2 40.9,106.2
  region: 41.675,106.2 41.675,113.2 41.375,113.2 41.375,106.2
  region: 42.275,106.2 42.275,113.2 41.9,113.2 41.9,106.2
  region: 40.125,106.2 40.125,113.2 40.05,113.2 40.05,106.2
  rectangle: 71.2,106.8 75.7,110.1
  region: 43.175,110.1 43.175,106.675 48.4,106.675 48.4,110.1
  rectangle: 33.966,3.3 34.325,5.3
  rectangle: 52.062,3.3 52.425,5.3
  region: 46.758,6.444 46.578,6.624 44.602,4.648 44.782,4.469
  rectangle: 44.602,4.648 44.856,5.537
  region: 45.019,4.232 45.198,4.052 47.174,6.028 46.994,6.208
  region: 46.087,4.052 46.087,4.306 45.198,4.306 45.198,4.052
  region: 78.733,105.057 78.479,105.057 78.479,102.263 78.733,102.263
  region: 77.85,104.428 78.03,104.248 78.658,104.877 78.479,105.057
  rectangle: 79.067,102.263 79.321,105.057
  region: 79.321,105.057 79.142,104.877 79.77,104.248 79.95,104.428
  region: 3.133,105.057 2.879,105.057 2.879,102.263 3.133,102.263
  region: 2.25,104.428 2.43,104.248 3.058,104.877 2.879,105.057
  rectangle: 3.467,102.263 3.721,105.057
  region: 3.721,105.057 3.542,104.877 4.17,104.248 4.35,104.428
  region: 70.8,17.659 70.8,36.175 68.45,36.175 68.45,17.659
  rectangle: 69.5,41.167 70.322,46.247
  rectangle: 25.369,14.776 41.346,15.691
  rectangle: 25.369,8.089 41.346,9.004
  rectangle: 68.981,8.089 70.835,15.684
  region: 27.274,15.691 25.369,15.691 25.369,8.089 27.274,8.089
  lines w0.076: 28.4,4.9 28.781,5.154 28.527,5.154 29.035,5.535 ; 28.781,5.281 29.035,5.535 ; 28.781,5.408 29.035,5.535 ; 54.293,4.75 54.674,5.004 54.42,5.004 54.928,5.385 ; 54.674,5.131 54.928,5.385 ; 54.674,5.258 54.928,5.385
  lines w0.127: 27.385,4.363 28.018,4.363 ; 28.018,4.403 28.618,4.403 ; 28.058,4.143 28.618,4.37 ; 28.058,4.597 28.618,4.37 ; 28.068,4.283 28.618,4.393 ; 28.068,4.457 28.618,4.347 ; 28.618,3.97 28.618,4.77 ; 28.618,4.363 29.211,4.363 ; 53.278,4.213 53.911,4.213 ; 53.911,4.253 54.511,4.253 ; 53.951,3.993 54.511,4.22 ; 53.951,4.447 54.511,4.22 ; 53.961,4.133 54.511,4.243 ; 53.961,4.307 54.511,4.197 ; 54.511,3.82 54.511,4.62 ; 54.511,4.213 55.104,4.213 ; 57.406,27.797 57.92,28.505 ; 58.132,25.095 58.646,25.802 ; 28.618,4.37 28.018,4.77 28.018,3.97 28.618,4.37 ; 54.511,4.22 53.911,3.82 53.911,4.62 54.511,4.22
  lines w0.2: 82.1,106.3 82.1,106.7 ; 75.7,113.1 82.1,113.1 ; 75.7,113.1 75.7,106.7 82.1,106.7 ; 75.7,113.1 82.1,113.1 ; 82.1,106.7 82.1,113.1
  text "Xilinx®  Virtex 4™" at 47.3,110.4 h3.2
  text "XC4VSX35-FFG668C" at 48.443,107.648 h2.6
  text "SRAM-256Kx16" at 59.787,94.046 h1.27
  text "DRAM-16Mx16" at 37.656,93.538 h1.27
  text "FLASH" at 63.274,70.287 h0.86
  text "1831" at 69.123,42.461 h1.02 r90
  text "SRAM-256Kx16" at 65.738,20.546 h1.27 r90
  text "DB46.03" at 26.106,12.407 h2.5
  text "XC4VSX35-FFG668C" at 26.106,10.934 h1.52
  text "Xilinx Daughter Board" at 26.119,9.004 h1.52
  text "DB46.03" at 41.295,8.089 h1.52
  text "PROGRAM" at 29.083,1.524 h1.4
  text "POWER" at 48.133,1.524 h1.4
Bottom Overlay:
  drawing of 1206 lines, arcs and shapes, not listed
  text "Xilinx®  Virtex 4™" at 72.4,110.4 h3.2
  text "XC4VSX35-FFG668C" at 71.1,107.648 h2.6
  text "SRAM-256Kx16" at 74.671,94.041 h1.27
  text "DRAM-16Mx16" at 50.744,93.538 h1.27
  text "AD BUILD No:" at 27.325,93.086 h0.86
  text ".Application_BuildNumber" at 18.489,92.985 h1.52
  text "REVISION No:" at 26.913,91.579 h0.86
  text "SVN 9252" at 18.489,91.478 h1.52
  text "PCB MANUFACTURER:" at 32.25,90.02 h0.86
  text "MANUFACTURE" at 12.533,88.294 h1.02
  text "DATE" at 12.561,86.597 h1.02
  text "COMPLIANCE:" at 30.032,78.269 h1.14
  text "CLASS 2" at 10.982,75.983 h1.02
  text "IPC-A-600G" at 27.746,75.983 h1.02
  text "MAX" at 37.77,74.588 h0.56 r270
  text "8860" at 36.901,74.371 h0.64 r270
  text "CLASS 2" at 10.982,73.951 h1.02
  text "TYPE 3" at 17.332,73.951 h1.02
  text "IPC-6012D" at 27.746,73.951 h1.02
  text "DS2406" at 68.864,70.48 h0.71 r270
  text "1" at 2.97,57.72 h1
  text "1" at 27.57,57.32 h1
  text "SRAM-256Kx16" at 69.471,19.911 h1.27 r270
  text "1" at 27.27,6.72 h1
  text "DB46" at 10.469,3.141 h3.05
Bottom Solder:
  region: 62.377,48.776 62.377,51.824 58.567,51.824 58.567,48.776
PCB Boundary:
  lines w0.1: 38.7,113.2 82.2,113.2 ; 38.7,113.2 82.2,113.2 ; 38.7,113.2 0,113.2 0,0 41.1,0 82.2,0 82.2,113.2 ; 38.7,113.2 82.2,113.2 ; 38.7,113.2 82.2,113.2
Mechanical 7:
  lines w0.2: 60.885,45.166 56.4,48.4 56.4,53.4 60.885,56.634 ; 64.7,50.9 66.7,50.9 ; 65.7,49.9 65.7,51.9 ; 70.615,45.166 75.1,48.4 75.1,53.4 70.615,56.634
Keep Away From Edge:
  lines w0.2: 5.08,5.08 76.962,5.08 76.962,107.95 5.08,107.95 5.08,5.08

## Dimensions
7.8,11.1 to 21.8,12 on Dimensions
74.4,12 to 74.4,62.8 on Dimensions
78.9,109.9 to 82.2,0 on Dimensions
3.3,110.3 to 0,0.4 on Dimensions
7.8,-0.4 to 0,108.6 on Dimensions
82.2,0 to 0,103.1 on Dimensions
0,113.2 to -0.5,0 on Dimensions
74.4,12 to 82.2,-0.1 on Dimensions
41.1,3.9 to 82.2,0.5 on Dimensions
7.8,11.1 to -0.5,0 on Dimensions
41.1,3.3 to 82.4,0 on Dimensions
74.4,12 to 82.4,0 on Dimensions
72.794,113.2 to 78.9,109.9 on Dimensions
